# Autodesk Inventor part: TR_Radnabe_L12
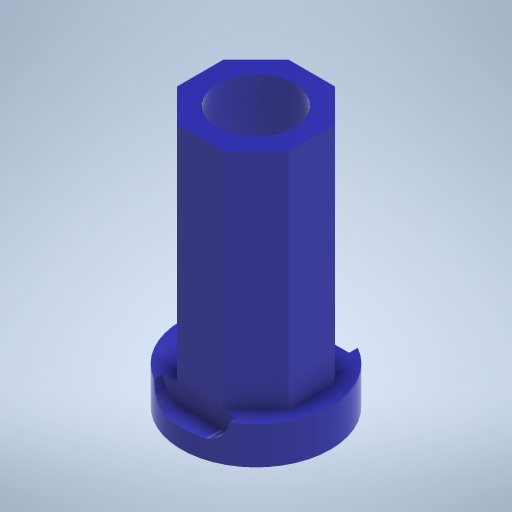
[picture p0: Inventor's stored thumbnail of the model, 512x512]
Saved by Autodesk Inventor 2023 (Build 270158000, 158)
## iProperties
Created: 2023-11
Part Number: TR_Radnabe_L12
Material: PC/ABS-Kunststoff
Document SubType Name: Modeling
Designer: Administrator
Density: 0.357273 g/cm^3
Appearance: Glatt - Marine
Author: Administrator
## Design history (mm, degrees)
sketch "Skizze1"
  geometry: L1 (1.243, -3)-(-1.243, -3); L2 (-1.243, -3)-(-3, -1.243); L3 (-3, -1.243)-(-3, 1.243); L4 (-3, 1.243)-(-1.243, 3); L5 (-1.243, 3)-(1.243, 3); L6 (1.243, 3)-(3, 1.243); L7 (3, 1.243)-(3, -1.243); L8 (3, -1.243)-(1.243, -3); C1 r 2.05 at (0, 0); 2 further points
  constraints: 16 end point, 2 coincident, 1 centre point, 1 horizontal, 17 other
  dimensions: "d0" = 6 distance between parallel lines of L7 L3 (= AchteckUmkreis); "d1" = 4.1 diameter of C1 (= DAchsAufnahme)
extrude "Extrusion1" new body sketch "Skizze1" distance "d2" = 12; taper "d3" = 0 deg
sketch "Skizze2" dims "DAchsAufnahme" = 4.1 [user parameter; used in 1 equation term]
  geometry: C1 r 4 at (0, 0); C2 r 2.05 at (0, 0); 1 further point
  constraints: 2 centre point, 2 coincident
  dimensions: "d4" = 8 diameter of C1
extrude "Extrusion2" join sketch "Skizze2" distance "d5" = 2; taper "d6" = 0 deg
sketch "Skizze3"
  geometry: L1 (-4.243, 0)-(-1.757, 0) reference; L2 (-5, 0)-(-1, 0); L3 (-2, -1)-(-4, -1); L4 (-1.757, 0)-(0, 0) reference; A1 r 1 centre (-4, 0) between (-5, 0) and (-4, -1); A2 r 1 centre (-2, 0) between (-2, -1) and (-1, 0); 11 further points
  constraints: 4 end point, 4 point on circle, 3 midpoint, 2 centre point, 2 horizontal, 2 tangent, 1 coincident, 1 equal radius, 1 parallel, 1 point on line, 10 other
  dimensions: "d7" = 1 radius of A1 (derived); "d8" = 4 distance of point (-1, 0) point (-5, 0); "d9" = 1 distance between parallel lines of L3 L2
extrude "Extrusion4" cut sketch "Skizze3" distance "d12" = 2; taper "d13" = 0 deg
mirror "Spiegeln2"
node "Volumenkörper1"
other parameters: "Radius" = 2.075 [user parameter], "Fasen" = 0.5 [user parameter], "Dicke" = 0.8 [user parameter], "Breitloch" = 2 [user parameter], "Langloch" = 32 [user parameter], "AchteckUmkreis" = 6 [user parameter; used in 1 equation term], "AchsDurchmesser" = 4 [user parameter], "AchsFase" = 0.5 [user parameter]
